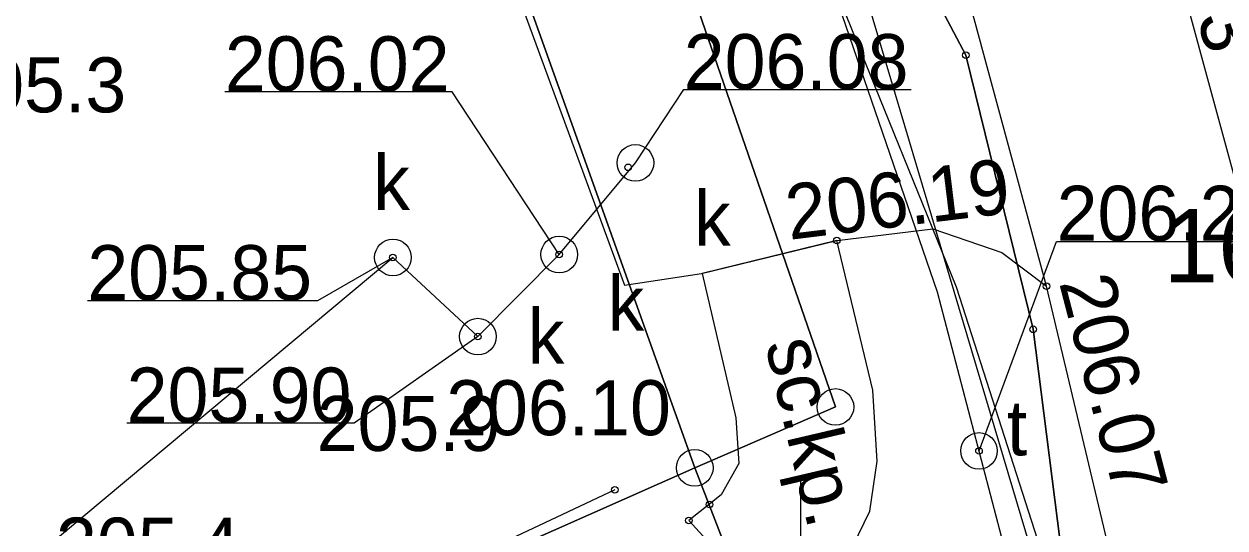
# Model space of a CAD drawing. Extents: x 6512400 to 6513200, y 6022500 to 6022750.
# Drawn here: x 6512839.39 to 6512855.79, y 6022601.8 to 6022608.68 of the extents above; entities that cross this region are included whole.
import ezdxf

# ---------------------------------------------------------------- set-up
doc = ezdxf.new("R2010")
doc.units = 0
for name, color, linetype in [('202-punkt graniczny', 7, 'Continuous'), ('203-punkt graniczny', 7, 'Continuous'), ('211-numer działki ewidencyjnej', 7, 'Continuous'), ('216-obręb ewidencyjny', 7, 'Continuous'), ('217-kontur klasyfikacyjny', 7, 'Continuous'), ('218-kontur użytku gruntowego', 7, 'Continuous'), ('219-działka ewidencyjna', 7, 'Continuous'), ('jezdnia (powierzchnia)', 7, 'Continuous'), ('krawężnik (linia)', 7, 'Continuous'), ('ogrodzenie trwałe', 7, 'Continuous'), ('pikieta naturalna', 7, 'Continuous'), ('pikieta naturalna-Atr2', 7, 'Continuous'), ('pikieta sztuczna', 7, 'Continuous'), ('pikieta sztuczna-Atr2', 7, 'Continuous'), ('przewód elektroenergetyczny (linia)', 7, 'Continuous'), ('przewód kanalizacyjny', 7, 'Continuous'), ('przewód kanalizacyjny (linia)', 7, 'Continuous'), ('przewód telekomunikacyjny (linia)', 7, 'Continuous'), ('punkt o określonej wysokości (sieć kanalizacyjna)', 7, 'Continuous'), ('punkt o określonej wysokości (sieć kanalizacyjna)-Atr2', 7, 'Continuous'), ('punkt o określonej wysokości (sieć telekomunikacyjna)', 7, 'Continuous'), ('punkt o określonej wysokości (sieć telekomunikacyjna)-Atr2', 7, 'Continuous'), ('punkt wysokościowy naturalny-Atr2', 7, 'Continuous'), ('punkt wysokościowy sztuczny', 7, 'Continuous'), ('punkt wysokościowy sztuczny-Atr2', 7, 'Continuous'), ('Wstawianie ramki sekcyjnej z opisem', 7, 'Continuous'), ('właz okrągły - siec kanalizacyjna (punkt)', 7, 'Continuous'), ('właz okrągły - siec kanalizacyjna (punkt)-Atr17', 7, 'Continuous'), ('właz okrągły - siec telekomunikacyjna (punkt)', 7, 'Continuous'), ('właz okrągły - siec telekomunikacyjna (punkt)-Atr17', 7, 'Continuous'), ('ścieżka (powierzchnia)', 7, 'Continuous'), ('ścieżka (powierzchnia)-Atr17', 7, 'Continuous')]:
    doc.layers.add(name, color=color, linetype=linetype)

# ---------------------------------------------------------------- blocks, each defined once
blk = doc.blocks.new('202')
blk.add_circle((0, 0), 0.25)
blk = doc.blocks.new('203')
blk.add_circle((0, 0), 0.045)
blk = doc.blocks.new('US22')
blk.add_circle((0, 0), 0.25)
blk = doc.blocks.new('PW02')
blk.add_circle((0, 0), 0.045)
blk = doc.blocks.new('PW01')
blk.add_circle((0, 0), 0.045)
blk = doc.blocks.new('RAMKA500K')
blk.add_line((50, 97.5), (50, 102.5))

msp = doc.modelspace()

# ---------------------------------------------------------------- linework, layer by layer
at = {"layer": '216-obręb ewidencyjny'}
for points in [[(6512836.687, 6022675.173), (6512833.61, 6022675.02), (6512828.67, 6022670.98), (6512801.96, 6022670.34), (6512810.18, 6022663.28), (6512825.37, 6022649.66), (6512838.47, 6022634.29), (6512852.25, 6022608.25), (6512853.17, 6022604.51), (6512855.78, 6022583.95), (6512858.85, 6022571.74), (6512828.23, 6022562.62), (6512818.47, 6022559.72), (6512824.714, 6022553.406)], [(6512780.7, 6022581.02), (6512806.2, 6022572.11), (6512806.62, 6022563.51), (6512811.41, 6022558.95), (6512818.47, 6022559.72), (6512828.23, 6022562.62), (6512858.85, 6022571.74), (6512855.78, 6022583.95), (6512853.17, 6022604.51), (6512852.25, 6022608.25), (6512838.47, 6022634.29), (6512825.37, 6022649.66), (6512810.18, 6022663.28), (6512801.96, 6022670.34), (6512796.96, 6022674.74), (6512790.49, 6022674.74), (6512785.56, 6022674.74), (6512768.24, 6022674.27)]]:
    msp.add_lwpolyline(points, dxfattribs=at)
at = {"layer": '217-kontur klasyfikacyjny'}
for points in [[(6512848.55, 6022602.62), (6512837.41, 6022633.76)], [(6512811.09, 6022586.02), (6512848.55, 6022602.62)], [(6512848.55, 6022602.62), (6512811.09, 6022586.02)], [(6512855.78, 6022583.95), (6512848.55, 6022602.62)]]:
    msp.add_lwpolyline(points, dxfattribs=at)
at = {"layer": '218-kontur użytku gruntowego'}
for points in [[(6512852.25, 6022608.25), (6512838.47, 6022634.29)], [(6512838.47, 6022634.29), (6512852.25, 6022608.25)], [(6512848.55, 6022602.62), (6512837.41, 6022633.76)], [(6512837.41, 6022633.76), (6512848.55, 6022602.62)], [(6512850.47, 6022603.45), (6512842.84, 6022625.52)], [(6512842.84, 6022625.52), (6512850.47, 6022603.45)], [(6512853.17, 6022604.51), (6512852.25, 6022608.25)], [(6512852.25, 6022608.25), (6512853.17, 6022604.51)], [(6512855.78, 6022583.95), (6512853.17, 6022604.51)], [(6512853.17, 6022604.51), (6512855.78, 6022583.95)], [(6512848.55, 6022602.62), (6512850.47, 6022603.45)], [(6512850.47, 6022603.45), (6512848.55, 6022602.62)], [(6512811.09, 6022586.02), (6512848.55, 6022602.62)], [(6512848.55, 6022602.62), (6512811.09, 6022586.02)], [(6512848.55, 6022602.62), (6512855.78, 6022583.95)], [(6512855.78, 6022583.95), (6512848.55, 6022602.62)]]:
    msp.add_lwpolyline(points, dxfattribs=at)
at = {"layer": '219-działka ewidencyjna'}
for points in [[(6512838.47, 6022634.29), (6512852.25, 6022608.25)], [(6512848.55, 6022602.62), (6512837.41, 6022633.76)], [(6512842.84, 6022625.52), (6512850.47, 6022603.45)], [(6512853.17, 6022604.51), (6512852.25, 6022608.25)], [(6512855.78, 6022583.95), (6512853.17, 6022604.51)], [(6512850.47, 6022603.45), (6512848.55, 6022602.62)], [(6512811.09, 6022586.02), (6512848.55, 6022602.62)], [(6512855.78, 6022583.95), (6512848.55, 6022602.62)]]:
    msp.add_lwpolyline(points, dxfattribs=at)
at = {"layer": 'jezdnia (powierzchnia)'}
msp.add_lwpolyline([(6512850.75, 6022614.71), (6512850.26, 6022613.71), (6512849.8, 6022613.04), (6512849.09, 6022612.33), (6512848.25, 6022611.75), (6512847.02, 6022611.04), (6512845.61, 6022610.5), (6512847.59, 6022605.11), (6512848.64, 6022605.27), (6512850.49, 6022605.72), (6512851.8, 6022605.88), (6512852.74, 6022605.56), (6512853.35, 6022605.1), (6512852.88, 6022606.85)], close=True, dxfattribs=at)
at = {"layer": 'krawężnik (linia)'}
msp.add_lwpolyline([(6512858.01, 6022586.22), (6512857.23, 6022588.81), (6512855.05, 6022597.75), (6512854.71, 6022599.38), (6512853.35, 6022605.1)], dxfattribs=at)
at = {"layer": 'ogrodzenie trwałe'}
msp.add_lwpolyline([(6512847.46, 6022602.32), (6512839.9, 6022598.76), (6512838.38, 6022602.97)], dxfattribs=at)
at = {"layer": 'przewód elektroenergetyczny (linia)'}
for points in [[(6512763.38, 6022676.06), (6512798.79, 6022676.04), (6512803.06, 6022673.02), (6512807.84, 6022668.96), (6512815.24, 6022662.53), (6512819.98, 6022657.77), (6512831.6, 6022645.79), (6512834.59, 6022642.25), (6512837.06, 6022638.75), (6512840.02, 6022634.13), (6512842.26, 6022630.04), (6512846.03, 6022621.35), (6512846.58, 6022618.9), (6512847.6, 6022616.23), (6512852.12, 6022605.09), (6512853.39, 6022601.13), (6512855.57, 6022592.48), (6512858.1, 6022582.86), (6512868.09, 6022584.49), (6512870.03, 6022584.23), (6512871.36, 6022584.34), (6512875.65, 6022585.56), (6512879.74, 6022586.61), (6512881.754, 6022587.357)], [(6512802.27, 6022673.66), (6512807.42, 6022670.09), (6512811.38, 6022666.87), (6512814.66, 6022663.43), (6512826.4, 6022651.65), (6512827.82, 6022650.09), (6512834.03, 6022642.46), (6512842.84, 6022631.19), (6512844.67, 6022626.95), (6512847.57, 6022619.87), (6512849.81, 6022612.67), (6512853.56, 6022600.08), (6512856.46, 6022588.83), (6512861.26, 6022569.82), (6512861.768, 6022567.654)]]:
    msp.add_lwpolyline(points, dxfattribs=at)
at = {"layer": 'przewód kanalizacyjny'}
msp.add_lwpolyline([(6512821.92, 6022592.3), (6512839.38, 6022601.27), (6512844.43, 6022605.49), (6512845.59, 6022604.41), (6512846.7, 6022605.53), (6512847.74, 6022606.78)], dxfattribs=at)
at = {"layer": 'przewód kanalizacyjny (linia)'}
msp.add_lwpolyline([(6512861.16, 6022586.16), (6512858.32, 6022597.78), (6512853.7, 6022614.72)], dxfattribs=at)
at = {"layer": 'przewód telekomunikacyjny (linia)'}
msp.add_lwpolyline([(6512836.6, 6022638.32), (6512844.42, 6022625.21), (6512848.91, 6022613.6), (6512851.86, 6022605.02), (6512853.91, 6022597.19), (6512860.14, 6022571.94), (6512860.33, 6022571.18)], dxfattribs=at)
at = {"layer": 'punkt o określonej wysokości (sieć kanalizacyjna)-Atr2'}
for points in [[(6512847.74, 6022606.78), (6512848.4, 6022607.78), (6512851.504, 6022607.78)], [(6512846.7, 6022605.53), (6512845.24, 6022607.75), (6512842.136, 6022607.75)], [(6512844.43, 6022605.49), (6512843.4, 6022604.9), (6512840.259, 6022604.9)], [(6512845.59, 6022604.41), (6512843.9, 6022603.23), (6512840.796, 6022603.23)]]:
    msp.add_lwpolyline(points, dxfattribs=at)
at = {"layer": 'punkt o określonej wysokości (sieć telekomunikacyjna)-Atr2'}
msp.add_lwpolyline([(6512852.43, 6022602.85), (6512853.49, 6022605.71), (6512856.307, 6022605.71)], dxfattribs=at)
at = {"layer": 'ścieżka (powierzchnia)'}
msp.add_lwpolyline([(6512848.65, 6022605.27), (6512849.11, 6022603.3), (6512849.15, 6022602.68), (6512848.91, 6022602.25), (6512848.47, 6022601.9), (6512849.72, 6022600.53), (6512850.2, 6022600.87), (6512850.63, 6022601.39), (6512850.94, 6022602.03), (6512851.04, 6022602.71), (6512850.98, 6022603.68), (6512850.49, 6022605.72)], close=True, dxfattribs=at)

# ---------------------------------------------------------------- block references
at = {"layer": '202-punkt graniczny'}
for p in [(6512850.47, 6022603.45), (6512848.55, 6022602.62)]:
    msp.add_blockref('202', p, dxfattribs=at)
at = {"layer": '203-punkt graniczny'}
for p in [(6512852.25, 6022608.25), (6512853.17, 6022604.51)]:
    msp.add_blockref('203', p, dxfattribs=at)
at = {"layer": 'pikieta naturalna'}
msp.add_blockref('PW01', (6512847.46, 6022602.32), dxfattribs=at)
at = {"layer": 'pikieta sztuczna'}
msp.add_blockref('PW01', (6512848.47, 6022601.9), dxfattribs=at)
at = {"layer": 'punkt o określonej wysokości (sieć kanalizacyjna)'}
for p in [(6512847.64, 6022606.72), (6512844.43, 6022605.49), (6512846.7, 6022605.53), (6512845.59, 6022604.41)]:
    msp.add_blockref('PW01', p, dxfattribs=at)
at = {"layer": 'punkt o określonej wysokości (sieć telekomunikacyjna)', "rotation": -75.328}
msp.add_blockref('PW01', (6512852.43, 6022602.85), dxfattribs=at)
at = {"layer": 'punkt wysokościowy sztuczny'}
for p in [(6512850.49, 6022605.72), (6512853.35, 6022605.1), (6512848.75, 6022602.12)]:
    msp.add_blockref('PW02', p, dxfattribs=at)
at = {"layer": 'Wstawianie ramki sekcyjnej z opisem'}
msp.add_blockref('RAMKA500K', (6512800, 6022500), dxfattribs=at)
at = {"layer": 'właz okrągły - siec kanalizacyjna (punkt)'}
for p in [(6512847.74, 6022606.78), (6512844.43, 6022605.49), (6512846.7, 6022605.53), (6512845.59, 6022604.41)]:
    msp.add_blockref('US22', p, dxfattribs=at)
at = {"layer": 'właz okrągły - siec telekomunikacyjna (punkt)', "rotation": -75.328}
msp.add_blockref('US22', (6512852.43, 6022602.85), dxfattribs=at)

# ---------------------------------------------------------------- texts
at = {"layer": '211-numer działki ewidencyjnej'}
msp.add_text('160/1', height=1, dxfattribs=at).set_placement((6512854.95, 6022605.15))
at = {"layer": 'pikieta naturalna-Atr2'}
for s, p in [('205.9', (6512843.39, 6022602.85)), ('205.4', (6512839.83, 6022601.19))]:
    msp.add_text(s, height=0.75, dxfattribs=at).set_placement(p)
at = {"layer": 'pikieta sztuczna-Atr2'}
msp.add_text('206.10', height=0.75, dxfattribs=at).set_placement((6512845.157, 6022603.065))
at = {"layer": 'punkt o określonej wysokości (sieć kanalizacyjna)-Atr2'}
for s, p in [('206.02', (6512842.136, 6022607.758)), ('206.08', (6512848.4, 6022607.788)), ('205.85', (6512840.259, 6022604.908)), ('205.90', (6512840.796, 6022603.238))]:
    msp.add_text(s, height=0.75, dxfattribs=at).set_placement(p)
at = {"layer": 'punkt o określonej wysokości (sieć telekomunikacyjna)-Atr2'}
msp.add_text('206.21', height=0.75, dxfattribs=at).set_placement((6512853.49, 6022605.718))
at = {"layer": 'punkt wysokościowy naturalny-Atr2'}
msp.add_text('205.3', height=0.75, dxfattribs=at).set_placement((6512838.28, 6022607.47))
at = {"layer": 'punkt wysokościowy sztuczny-Atr2'}
for s, rotation, p in [('206.13', 285.965, (6512854.71, 6022611.18)), ('206.19', 6.963, (6512849.84, 6022605.73)), ('206.07', 284.642, (6512853.52, 6022605.15))]:
    msp.add_text(s, height=0.75, rotation=rotation, dxfattribs=at).set_placement(p)
at = {"layer": 'właz okrągły - siec kanalizacyjna (punkt)-Atr17'}
for p in [(6512844.16, 6022606.14), (6512848.54, 6022605.65), (6512847.36, 6022604.49), (6512846.27, 6022604.04)]:
    msp.add_text('k', height=0.75, dxfattribs=at).set_placement(p)
at = {"layer": 'właz okrągły - siec telekomunikacyjna (punkt)-Atr17'}
msp.add_text('t', height=0.75, dxfattribs=at).set_placement((6512852.81, 6022602.79))
at = {"layer": 'ścieżka (powierzchnia)-Atr17'}
msp.add_text('sc.kp.', height=0.75, rotation=283.143, dxfattribs=at).set_placement((6512849.51, 6022604.31))

doc.saveas('drawing.dxf')
